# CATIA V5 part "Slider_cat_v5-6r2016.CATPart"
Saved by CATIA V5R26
Part number: Slider
Bounding box of the stored display mesh (mm): x -10 to 10, y -69.282 to 69.282, z -70 to 10
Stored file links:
  D:\_Deepak\CATIA\CATIA V5 2015 Parts Files\Tutorial Files\Tutorials\c16_catia_v5_6r2016_tut\Slide Curve\Slider_cat_v5-6r2012.CATPart
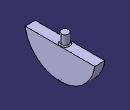
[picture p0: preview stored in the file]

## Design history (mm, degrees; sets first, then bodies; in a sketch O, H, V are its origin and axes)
Body1 (main body)
  Sketch1 on yz-plane, origin (0, 0, 0), H (0, 1, 0), V (0, 0, 1)
    arc A1 centre (0, 0) radius 70 from (-69.282, -10) to (69.282, -10) ccw
    point P1 (0, 0)
    point P2 (-69.282, -10)
    point P3 (69.282, -10)
    point P4 (0, 0)
    point P5 (-69.282, -10)
    line L1 (-69.282, -10) -> (69.282, -10)
    point P6 (69.282, -10)
    point P7 (-69.282, -10)
    reference intersected line E1 through (0, 0) direction (-1, 0) from xy-plane
    reference intersected line E3 through (0, 0) direction (0, 1) from zx-plane
    radius A1 = 70
    distance L1 P1 = 10
    coincidence: P1 V, P4 V, P6 P3, P7 A1, P2 P7, E3 P1, P2 L1, P3 L1, H P4, P2 P5, P1 H
    horizontal: L1 H, E1 H
    vertical: E3 V
    perpendicularity: E3 L1
  Pad1: profile Sketch1, direction (1, 0, 0), length 10, mirrored extent
  Point1: type OnCurve, Support edge [face of Pad1 from Sketch1.A1 | end face of Pad1], Ratio 0.5
  Sketch2 on face of Pad1 from Sketch1.L1, origin (0, 0, -10), H (1, 0, 0), V (0, 1, 0)
    circle A1 centre (0, 0) radius 7.5
    point P1 (0, 0)
    reference projected line E1 (10, 69.282) -> (10, -69.282) from edge [face of Pad1 from Sketch1.L1 | end face of Pad1]
    radius A1 = 7.5
    distance P1 E1 = 10
    coincidence: P1 H
  Pad2: profile Sketch2, direction (0, 0, 1), length 20
  Fillet1: radius 2, on edge [face of Pad1 from Sketch1.L1 | face of Pad2 from Sketch2.A1]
